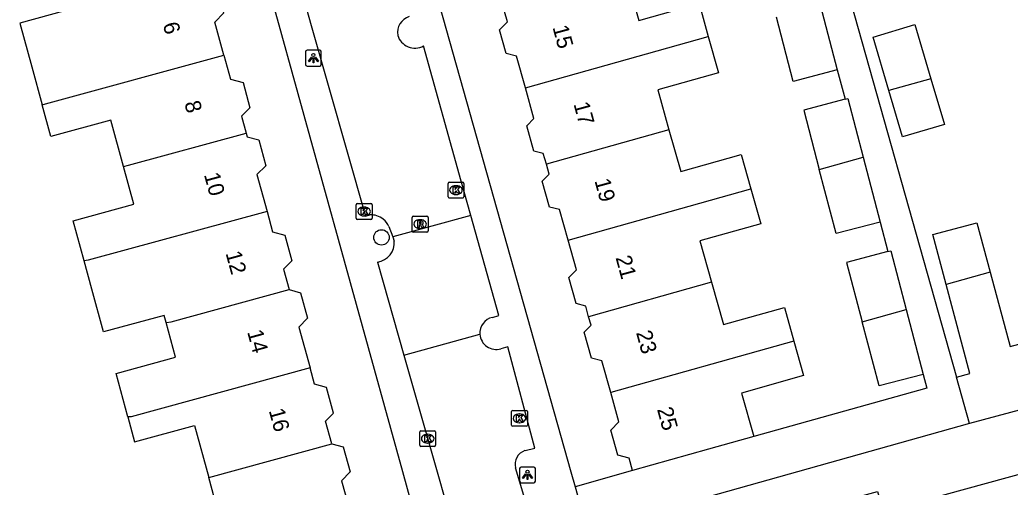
# Model space of a CAD drawing. Extents: x 162250 to 162654, y 380744 to 381605.
# Drawn here: x 162430.2 to 162492.9, y 381249 to 381278.7 of the extents above; entities that cross this region are included whole.
import ezdxf

# ---------------------------------------------------------------- set-up
doc = ezdxf.new("R2010")
doc.units = 0
for name, color, linetype in [('IMGEO_Boom', 7, 'Continuous'), ('IMGEO_Kolk', 7, 'Continuous'), ('IMGEO_Lichtpunt', 7, 'Continuous'), ('IMGEO_Pand', 7, 'Continuous'), ('IMGEO_Pand_nummerreeks', 7, 'Continuous'), ('IMGEO_Rijbaan_lokaal_open', 7, 'Continuous'), ('IMGEO_Rioolput', 7, 'Continuous'), ('IMGEO_Voetpad_open', 7, 'Continuous')]:
    doc.layers.add(name, color=color, linetype=linetype)

msp = doc.modelspace()

# ---------------------------------------------------------------- linework, layer by layer
at = {"layer": 'IMGEO_Boom'}
msp.add_circle((162453.079, 381264.867), 0.489, dxfattribs=at)
at = {"layer": 'IMGEO_Kolk'}
for p, q in [((162457.302, 381267.44), (162457.302, 381268.292)), ((162457.377, 381268.366), (162458.229, 381268.366)), ((162457.79, 381268.146), (162457.815, 381268.146)), ((162458.303, 381268.292), (162458.303, 381267.44)), ((162458.229, 381267.366), (162457.377, 381267.366)), ((162457.813, 381267.586), (162457.788, 381267.586)), ((162451.48, 381266.085), (162451.48, 381266.937)), ((162451.555, 381267.011), (162452.407, 381267.011)), ((162451.968, 381266.791), (162451.993, 381266.791)), ((162452.481, 381266.937), (162452.481, 381266.085)), ((162452.407, 381266.011), (162451.555, 381266.011)), ((162451.991, 381266.231), (162451.966, 381266.231)), ((162461.328, 381252.964), (162461.328, 381253.816)), ((162461.403, 381253.89), (162462.255, 381253.89)), ((162461.816, 381253.67), (162461.841, 381253.67)), ((162462.329, 381253.816), (162462.329, 381252.964)), ((162462.255, 381252.89), (162461.403, 381252.89)), ((162461.839, 381253.11), (162461.814, 381253.11)), ((162455.511, 381251.681), (162455.511, 381252.533)), ((162455.586, 381252.607), (162456.438, 381252.607)), ((162455.999, 381252.387), (162456.024, 381252.387)), ((162456.512, 381252.533), (162456.512, 381251.681)), ((162456.438, 381251.607), (162455.586, 381251.607)), ((162456.022, 381251.827), (162455.997, 381251.827))]:
    msp.add_line(p, q, dxfattribs=at)
for points in [[(162457.302, 381267.44), (162457.302, 381268.292)], [(162457.377, 381268.366), (162458.229, 381268.366)], [(162457.623, 381268.066), (162457.746, 381268.066), (162457.746, 381267.915), (162457.876, 381268.066), (162458.04, 381268.066), (162457.894, 381267.915), (162458.047, 381267.666), (162457.895, 381267.666), (162457.81, 381267.83), (162457.746, 381267.763), (162457.746, 381267.666), (162457.623, 381267.666), (162457.623, 381268.066)], [(162458.303, 381268.292), (162458.303, 381267.44)], [(162458.229, 381267.366), (162457.377, 381267.366)], [(162451.48, 381266.085), (162451.48, 381266.937)], [(162451.555, 381267.011), (162452.407, 381267.011)], [(162451.801, 381266.711), (162451.924, 381266.711), (162451.924, 381266.56), (162452.054, 381266.711), (162452.218, 381266.711), (162452.072, 381266.56), (162452.225, 381266.311), (162452.073, 381266.311), (162451.988, 381266.475), (162451.924, 381266.408), (162451.924, 381266.311), (162451.801, 381266.311), (162451.801, 381266.711)], [(162452.481, 381266.937), (162452.481, 381266.085)], [(162452.407, 381266.011), (162451.555, 381266.011)], [(162461.328, 381252.964), (162461.328, 381253.816)], [(162461.403, 381253.89), (162462.255, 381253.89)], [(162461.649, 381253.59), (162461.772, 381253.59), (162461.772, 381253.439), (162461.902, 381253.59), (162462.066, 381253.59), (162461.92, 381253.439), (162462.073, 381253.19), (162461.921, 381253.19), (162461.836, 381253.354), (162461.772, 381253.287), (162461.772, 381253.19), (162461.649, 381253.19), (162461.649, 381253.59)], [(162462.329, 381253.816), (162462.329, 381252.964)], [(162462.255, 381252.89), (162461.403, 381252.89)], [(162455.511, 381251.681), (162455.511, 381252.533)], [(162455.586, 381252.607), (162456.438, 381252.607)], [(162455.832, 381252.307), (162455.955, 381252.307), (162455.955, 381252.156), (162456.085, 381252.307), (162456.249, 381252.307), (162456.103, 381252.156), (162456.256, 381251.907), (162456.104, 381251.907), (162456.019, 381252.071), (162455.955, 381252.004), (162455.955, 381251.907), (162455.832, 381251.907), (162455.832, 381252.307)], [(162456.512, 381252.533), (162456.512, 381251.681)], [(162456.438, 381251.607), (162455.586, 381251.607)]]:
    msp.add_lwpolyline(points, dxfattribs=at)
for centre, start, end in [((162457.379, 381268.29), 91.55205, 178.44795), ((162457.379, 381268.29), 91.55205, 178.44795), ((162458.227, 381268.29), 1.55205, 88.44795), ((162458.227, 381268.29), 1.55205, 88.44795), ((162457.379, 381267.442), 181.55205, 268.44795), ((162457.379, 381267.442), 181.55205, 268.44795), ((162458.227, 381267.442), 271.55205, 358.44795), ((162458.227, 381267.442), 271.55205, 358.44795), ((162451.557, 381266.935), 91.55205, 178.44795), ((162451.557, 381266.935), 91.55205, 178.44795), ((162452.405, 381266.935), 1.55205, 88.44795), ((162452.405, 381266.935), 1.55205, 88.44795), ((162451.557, 381266.087), 181.55205, 268.44795), ((162451.557, 381266.087), 181.55205, 268.44795), ((162452.405, 381266.087), 271.55205, 358.44795), ((162452.405, 381266.087), 271.55205, 358.44795), ((162461.405, 381253.814), 91.55205, 178.44795), ((162461.405, 381253.814), 91.55205, 178.44795), ((162462.253, 381253.814), 1.55205, 88.44795), ((162462.253, 381253.814), 1.55205, 88.44795), ((162461.405, 381252.966), 181.55205, 268.44795), ((162461.405, 381252.966), 181.55205, 268.44795), ((162462.253, 381252.966), 271.55205, 358.44795), ((162462.253, 381252.966), 271.55205, 358.44795), ((162455.588, 381252.531), 91.55205, 178.44795), ((162455.588, 381252.531), 91.55205, 178.44795), ((162456.436, 381252.531), 1.55205, 88.44795), ((162456.436, 381252.531), 1.55205, 88.44795), ((162455.588, 381251.683), 181.55205, 268.44795), ((162455.588, 381251.683), 181.55205, 268.44795), ((162456.436, 381251.683), 271.55205, 358.44795), ((162456.436, 381251.683), 271.55205, 358.44795)]:
    msp.add_arc(centre, 0.0765, start, end, dxfattribs=at)
for centre, major_axis, ratio, start_param, end_param in [((162457.789, 381267.866), (-0.387, 0.002), 0.722429, 4.712389, 7.853982), ((162457.814, 381267.866), (-0.39, 0.002), 0.717154, 1.570796, 4.712389), ((162451.967, 381266.511), (-0.387, 0.002), 0.722429, 4.712389, 7.853982), ((162451.992, 381266.511), (-0.39, 0.002), 0.717154, 1.570796, 4.712389), ((162461.815, 381253.39), (-0.387, 0.002), 0.722429, 4.712389, 7.853982), ((162461.84, 381253.39), (-0.39, 0.002), 0.717154, 1.570796, 4.712389), ((162455.998, 381252.107), (-0.387, 0.002), 0.722429, 4.712389, 7.853982), ((162456.023, 381252.107), (-0.39, 0.002), 0.717154, 1.570796, 4.712389)]:
    msp.add_ellipse(centre, major_axis=major_axis, ratio=ratio, start_param=start_param, end_param=end_param, dxfattribs=at)
at = {"layer": 'IMGEO_Lichtpunt'}
for p, q in [((162449.169, 381276.732), (162448.361, 381276.732)), ((162449.169, 381276.732), (162448.361, 381276.732)), ((162448.267, 381276.637), (162448.267, 381275.83)), ((162448.267, 381276.637), (162448.267, 381275.83)), ((162449.263, 381275.83), (162449.263, 381276.637)), ((162449.263, 381275.83), (162449.263, 381276.637)), ((162448.361, 381275.736), (162449.169, 381275.736)), ((162448.361, 381275.736), (162449.169, 381275.736)), ((162461.84, 381250.211), (162461.84, 381249.404)), ((162461.84, 381250.211), (162461.84, 381249.404)), ((162462.742, 381250.306), (162461.934, 381250.306)), ((162462.742, 381250.306), (162461.934, 381250.306)), ((162462.836, 381249.404), (162462.836, 381250.211)), ((162462.836, 381249.404), (162462.836, 381250.211)), ((162461.934, 381249.31), (162462.742, 381249.31)), ((162461.934, 381249.31), (162462.742, 381249.31))]:
    msp.add_line(p, q, dxfattribs=at)
for points in [[(162448.641, 381276.301), (162448.68, 381276.273), (162448.492, 381276.011), (162448.454, 381276.038), (162448.641, 381276.301)], [(162448.743, 381276.253), (162448.79, 381276.253), (162448.79, 381275.931), (162448.743, 381275.931), (162448.743, 381276.253)], [(162448.853, 381276.273), (162448.891, 381276.3), (162449.078, 381276.038), (162449.039, 381276.01), (162448.853, 381276.273)], [(162462.214, 381249.875), (162462.253, 381249.847), (162462.065, 381249.585), (162462.027, 381249.612), (162462.214, 381249.875)], [(162462.316, 381249.827), (162462.363, 381249.827), (162462.363, 381249.505), (162462.316, 381249.505), (162462.316, 381249.827)], [(162462.426, 381249.847), (162462.464, 381249.874), (162462.651, 381249.612), (162462.612, 381249.584), (162462.426, 381249.847)]]:
    msp.add_lwpolyline(points, dxfattribs=at)
for centre in [(162448.766, 381276.435), (162462.339, 381250.009)]:
    msp.add_circle(centre, 0.0994, dxfattribs=at)
for centre, start, end in [((162448.361, 381276.637), 90, 180), ((162448.361, 381276.637), 90, 180), ((162449.169, 381276.637), 0, 90), ((162449.169, 381276.637), 0, 90), ((162448.361, 381275.83), 180, 270), ((162448.361, 381275.83), 180, 270), ((162449.169, 381275.83), 270, 0), ((162449.169, 381275.83), 270, 360), ((162461.934, 381250.211), 90, 180), ((162461.934, 381250.211), 90, 180), ((162462.742, 381250.211), 0, 90), ((162462.742, 381250.211), 0, 90), ((162461.934, 381249.404), 180, 270), ((162461.934, 381249.404), 180, 270), ((162462.742, 381249.404), 270, 0), ((162462.742, 381249.404), 270, 360)]:
    msp.add_arc(centre, 0.0946, start, end, dxfattribs=at)
at = {"layer": 'IMGEO_Pand'}
for points in [[(162443.091, 381276.434), (162442.52, 381278.526), (162443.094, 381279.105), (162442.65, 381280.731), (162441.882, 381280.933), (162441.754, 381281.402)], [(162468.625, 381281.365), (162469.395, 381278.622), (162473.216, 381279.694), (162473.801, 381277.61)], [(162433.991, 381279.511), (162430.151, 381278.463), (162430.907, 381275.693), (162431.565, 381273.282)], [(162480.9, 381279.609), (162481.979, 381275.496)], [(162462.202, 381274.344), (162461.636, 381276.362), (162460.986, 381276.528), (162460.564, 381278.03), (162461.062, 381278.54), (162460.881, 381279.184)], [(162481.979, 381275.496), (162479.182, 381274.763), (162478.117, 381278.825)], [(162485.248, 381274.191), (162484.245, 381277.574), (162486.893, 381278.359), (162487.912, 381274.925)], [(162462.202, 381274.344), (162473.801, 381277.61)], [(162473.801, 381277.61), (162474.45, 381275.298), (162470.602, 381274.218), (162471.309, 381271.697)], [(162431.565, 381273.282), (162431.775, 381273.347), (162443.091, 381276.434)], [(162443.091, 381276.434), (162443.508, 381274.906), (162444.304, 381274.696), (162444.742, 381273.091), (162444.213, 381272.557), (162444.506, 381271.485)], [(162487.912, 381274.925), (162488.772, 381272.024), (162486.123, 381271.238), (162485.248, 381274.191)], [(162487.912, 381274.925), (162485.248, 381274.191)], [(162463.534, 381269.508), (162463.342, 381270.192), (162462.74, 381270.346), (162462.294, 381271.936), (162462.748, 381272.4), (162462.202, 381274.344)], [(162482.469, 381273.627), (162479.851, 381272.941), (162480.84, 381269.169)], [(162482.469, 381273.627), (162482.648, 381273.674), (162483.623, 381269.952)], [(162436.729, 381269.372), (162435.926, 381272.312), (162432.114, 381271.272), (162431.565, 381273.282)], [(162471.309, 381271.697), (162463.534, 381269.508)], [(162471.309, 381271.697), (162472.051, 381269.054), (162475.889, 381270.131), (162476.501, 381267.948)], [(162436.729, 381269.372), (162437.039, 381269.449), (162444.506, 381271.485)], [(162444.506, 381271.485), (162444.572, 381271.243), (162445.302, 381271.051), (162445.748, 381269.416), (162445.187, 381268.849), (162445.825, 381266.512)], [(162480.84, 381269.169), (162483.623, 381269.952)], [(162483.623, 381269.952), (162484.702, 381265.839)], [(162434.226, 381263.372), (162433.53, 381265.922), (162437.383, 381266.974), (162436.729, 381269.372)], [(162464.91, 381264.683), (162464.364, 381266.627), (162463.735, 381266.787), (162463.272, 381268.439), (162463.708, 381268.887), (162463.534, 381269.508)], [(162484.702, 381265.839), (162481.905, 381265.106), (162480.84, 381269.169)], [(162464.91, 381264.683), (162476.501, 381267.948)], [(162476.501, 381267.948), (162477.124, 381265.728), (162473.269, 381264.647), (162474.002, 381262.032)], [(162445.825, 381266.512), (162434.492, 381263.421), (162434.226, 381263.372)], [(162445.825, 381266.512), (162446.177, 381265.221), (162446.96, 381265.015), (162447.403, 381263.39), (162446.866, 381262.848), (162447.218, 381261.557)], [(162488.877, 381261.871), (162488.029, 381265.051), (162490.836, 381265.799), (162491.673, 381262.659)], [(162466.215, 381259.84), (162466.026, 381260.515), (162465.419, 381260.67), (162464.956, 381262.317), (162465.436, 381262.807), (162464.91, 381264.683)], [(162485.191, 381263.971), (162482.572, 381263.285), (162483.561, 381259.512)], [(162485.191, 381263.971), (162485.369, 381264.018), (162486.344, 381260.296)], [(162439.428, 381259.472), (162439.306, 381259.921), (162435.454, 381258.87), (162434.713, 381261.587), (162434.226, 381263.372)], [(162491.673, 381262.659), (162488.877, 381261.871)], [(162491.673, 381262.659), (162492.929, 381257.949), (162495.938, 381258.751), (162496.981, 381254.838), (162490.359, 381253.072)], [(162474.002, 381262.032), (162466.215, 381259.84)], [(162474.002, 381262.032), (162474.756, 381259.345), (162478.628, 381260.431), (162479.228, 381258.292)], [(162489.53, 381256.012), (162490.379, 381256.238), (162488.877, 381261.871)], [(162439.428, 381259.472), (162439.756, 381259.522), (162447.218, 381261.557)], [(162447.218, 381261.557), (162447.956, 381261.358), (162448.398, 381259.738), (162447.847, 381259.181), (162448.555, 381256.588)], [(162467.616, 381255.023), (162467.049, 381257.042), (162466.389, 381257.211), (162465.928, 381258.855), (162466.366, 381259.304), (162466.215, 381259.84)], [(162483.561, 381259.512), (162486.344, 381260.296)], [(162486.344, 381260.296), (162487.423, 381256.183)], [(162437.002, 381253.478), (162436.25, 381256.235), (162440.03, 381257.267), (162439.428, 381259.472)], [(162487.423, 381256.183), (162484.626, 381255.45), (162483.561, 381259.512)], [(162479.228, 381258.292), (162467.616, 381255.023)], [(162479.228, 381258.292), (162479.844, 381256.099), (162475.909, 381254.995), (162476.684, 381252.235)], [(162448.555, 381256.588), (162437.21, 381253.495), (162437.002, 381253.478)], [(162449.935, 381251.777), (162449.54, 381253.224), (162450.037, 381253.726), (162449.592, 381255.358), (162448.836, 381255.557), (162448.555, 381256.588)], [(162490.359, 381253.072), (162489.53, 381256.012)], [(162468.996, 381250.078), (162468.774, 381250.869), (162468.06, 381251.051), (162467.613, 381252.645), (162468.134, 381253.178), (162467.616, 381255.023)], [(162437.002, 381253.478), (162437.432, 381251.903), (162441.222, 381252.938), (162442.129, 381249.647)], [(162476.684, 381252.235), (162473.811, 381251.429), (162468.996, 381250.078)], [(162442.129, 381249.647), (162449.935, 381251.777)], [(162449.935, 381251.777), (162450.653, 381251.589), (162451.087, 381250), (162450.542, 381249.433), (162451.339, 381246.57)], [(162500, 381241.919), (162482.554, 381237.116), (162484.506, 381230.024), (162482.322, 381229.422), (162483.689, 381224.455), (162475.108, 381222.092), (162472.293, 381232.317), (162473.878, 381232.753), (162473.212, 381235.174), (162471.912, 381238.051), (162471.446, 381241.461), (162473.016, 381241.894), (162472.432, 381244.017), (162473.252, 381244.243), (162480.7, 381246.293), (162480.338, 381247.607), (162484.525, 381248.76), (162484.877, 381247.481), (162494.051, 381250)], [(162439.809, 381243.359), (162439.026, 381246.17), (162442.798, 381247.22), (162442.129, 381249.647)]]:
    msp.add_lwpolyline(points, dxfattribs=at)
at = {"layer": 'IMGEO_Rijbaan_lokaal_open'}
for points in [[(162445.283, 381293.103), (162445.029, 381292.889), (162444.632, 381292.625), (162448.633, 381278.311), (162452.067, 381266.212), (162452.335, 381266.293)], [(162458.743, 381266.259), (162458.136, 381268.433), (162455.748, 381277.006)], [(162458.743, 381266.259), (162453.799, 381264.901)], [(162460.113, 381259.798), (162460.516, 381259.911), (162458.743, 381266.259)], [(162453.545, 381265.56), (162453.799, 381264.901)], [(162453.799, 381264.901), (162453.893, 381264.638)], [(162452.824, 381263.305), (162454.505, 381257.402)], [(162454.505, 381257.402), (162459.32, 381258.724)], [(162462.18, 381251.345), (162462.795, 381251.509), (162461.085, 381257.923), (162460.654, 381257.809)], [(162454.505, 381257.402), (162456.613, 381250), (162457.141, 381248.145)], [(162463.064, 381245.338), (162461.583, 381250.246)]]:
    msp.add_lwpolyline(points, dxfattribs=at)
for centre, radius, start, end in [((162455.146, 381277.86), 1.051, 106.56084, 189.88036), ((162455.21, 381278.027), 1.154, 197.49194, 297.77594), ((162452.42, 381265.071), 1.225, 50.63589, 93.97609), ((162452.422, 381265.068), 1.226, 23.66453, 50.79244), ((162452.648, 381264.542), 1.249, 278.116, 4.42823), ((162460.347, 381258.795), 1.03, 103.15825, 183.9603), ((162460.35, 381258.795), 1.032, 183.95852, 287.14848), ((162462.439, 381250.492), 0.891, 106.92356, 196.05296)]:
    msp.add_arc(centre, radius, start, end, dxfattribs=at)
at = {"layer": 'IMGEO_Rioolput'}
for p, q in [((162455.03, 381265.283), (162455.03, 381266.135)), ((162455.105, 381266.209), (162455.957, 381266.209)), ((162456.031, 381266.135), (162456.031, 381265.283)), ((162455.541, 381265.429), (162455.516, 381265.429)), ((162455.518, 381265.989), (162455.543, 381265.989)), ((162455.957, 381265.209), (162455.105, 381265.209))]:
    msp.add_line(p, q, dxfattribs=at)
for points in [[(162455.03, 381265.283), (162455.03, 381266.135)], [(162455.105, 381266.209), (162455.957, 381266.209)], [(162456.031, 381266.135), (162456.031, 381265.283)], [(162455.619, 381265.907), (162455.367, 381265.909), (162455.367, 381265.509)], [(162455.367, 381265.509), (162455.491, 381265.509), (162455.491, 381265.671), (162455.502, 381265.671)], [(162455.545, 381265.828), (162455.491, 381265.828), (162455.491, 381265.747)], [(162455.491, 381265.747), (162455.543, 381265.747)], [(162455.549, 381265.642), (162455.62, 381265.509), (162455.76, 381265.509), (162455.695, 381265.635)], [(162455.957, 381265.209), (162455.105, 381265.209)]]:
    msp.add_lwpolyline(points, dxfattribs=at)
for centre, radius, start, end in [((162455.107, 381266.133), 0.0765, 91.55205, 178.44795), ((162455.107, 381266.133), 0.0765, 91.55205, 178.44795), ((162455.955, 381266.133), 0.0765, 1.55205, 88.44795), ((162455.955, 381266.133), 0.0765, 1.55205, 88.44795), ((162455.501, 381265.618), 0.0533, 26.02933, 88.69889), ((162455.527, 381265.936), 0.19, 274.7715, 282.96867), ((162455.551, 381265.732), 0.0964, 77.00612, 93.18647), ((162455.565, 381265.789), 0.0378, 276.66336, 79.67722), ((162455.618, 381265.797), 0.109, 350.36119, 89.41601), ((162455.616, 381265.797), 0.112, 277.58423, 350.98172), ((162455.6, 381265.582), 0.108, 29.51342, 73.79051), ((162455.107, 381265.285), 0.0765, 181.55205, 268.44795), ((162455.107, 381265.285), 0.0765, 181.55205, 268.44795), ((162455.955, 381265.285), 0.0765, 271.55205, 358.44795), ((162455.955, 381265.285), 0.0765, 271.55205, 358.44795)]:
    msp.add_arc(centre, radius, start, end, dxfattribs=at)
for centre, major_axis, ratio, start_param, end_param in [((162455.517, 381265.709), (-0.387, 0.002), 0.722429, 4.712389, 7.853982), ((162455.542, 381265.709), (-0.39, 0.002), 0.717154, 1.570796, 4.712389)]:
    msp.add_ellipse(centre, major_axis=major_axis, ratio=ratio, start_param=start_param, end_param=end_param, dxfattribs=at)
at = {"layer": 'IMGEO_Voetpad_open'}
for points in [[(162437.221, 381349.572), (162450.776, 381300.808), (162465.094, 381250), (162465.361, 381249.054)], [(162455.092, 381247.608), (162454.43, 381250), (162442.682, 381292.462)], [(162481.898, 381283.088), (162489.53, 381256.012)], [(162481.979, 381275.496), (162482.469, 381273.627)], [(162484.702, 381265.839), (162485.191, 381263.971)], [(162487.423, 381256.183), (162487.652, 381255.312), (162476.684, 381252.235)], [(162490.359, 381253.072), (162466.151, 381246.25)], [(162468.996, 381250.078), (162465.361, 381249.054)], [(162465.361, 381249.054), (162466.151, 381246.25)]]:
    msp.add_lwpolyline(points, dxfattribs=at)

# ---------------------------------------------------------------- texts
at = {"layer": 'IMGEO_Pand_nummerreeks'}
for s, rotation, p in [('6', 285.35506, (162439.204, 381278.379)), ('15', 285.30123, (162463.917, 381278.191)), ('8', 285.35316, (162440.574, 381273.389)), ('17', 285.30123, (162465.248, 381273.329)), ('10', 285.35316, (162441.82, 381268.846)), ('19', 285.30123, (162466.578, 381268.467)), ('12', 285.35316, (162443.189, 381263.866)), ('21', 285.30123, (162467.914, 381263.585)), ('14', 285.35316, (162444.559, 381258.876)), ('23', 285.30123, (162469.214, 381258.832)), ('25', 285.30123, (162470.544, 381253.97)), ('16', 285.35506, (162445.928, 381253.89))]:
    msp.add_text(s, height=1, rotation=rotation, dxfattribs=at).set_placement(p)

doc.saveas('drawing.dxf')
